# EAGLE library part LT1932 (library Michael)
Constant-Current DC/DC LED Driver in ThinSOT
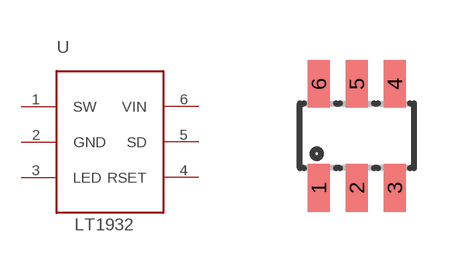
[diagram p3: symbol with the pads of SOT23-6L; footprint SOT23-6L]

Designator prefix -

## LT1932  [SOT23-6L]
1  SW
2  GND  pwr
3  LED
4  RSET
5  SD  in
6  VIN  pwr

## Footprint SOT23-6L (pad centres in mm)
Small Outline Transistor
smd 0.55 x 1.2: 1 -0.95,-1.3; 2 0,-1.3; 3 0.95,-1.3; 4 0.95,1.3; 5 0,1.3; 6 -0.95,1.3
